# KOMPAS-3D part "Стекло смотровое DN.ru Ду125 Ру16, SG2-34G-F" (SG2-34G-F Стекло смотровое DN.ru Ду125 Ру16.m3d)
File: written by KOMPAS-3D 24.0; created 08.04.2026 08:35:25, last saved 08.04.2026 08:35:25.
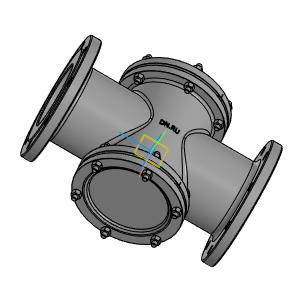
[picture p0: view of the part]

Document properties: Автор: Main; Полное имя файла: D:\DN.ru Аутсерс\Стекло смотровое DN.ru\SG2-34G-F Стекло смотровое DN.ru Ду125 Ру16\SG2-34G-F Стекло смотровое DN.ru Ду125 Ру16.m3d

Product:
- Part/product: Стекло смотровое DN.ru Ду125 Ру16  | designation SG2-34G-F
    Масса: 36
    Раздел спецификации: Прочие изделия
    Примечание: D500-00088

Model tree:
1. Операция без истории:1

Expressions: SG2-34G-F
